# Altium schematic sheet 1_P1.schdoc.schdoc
size 309 x 223 mm; Symbol: Sheet-Symbol_A4; Device: Sheet-Symbol_A4; @Page Name: P1; @Create Date: 2023-12-06; @Page Count: 1; @Page No: 1; @Project Name: TauKeyboard; @Schematic Name: KeyboardCore; @Update Date: 2023-12-06; Company: 嘉立创EDA; Page Size: A4; Version: V1.0
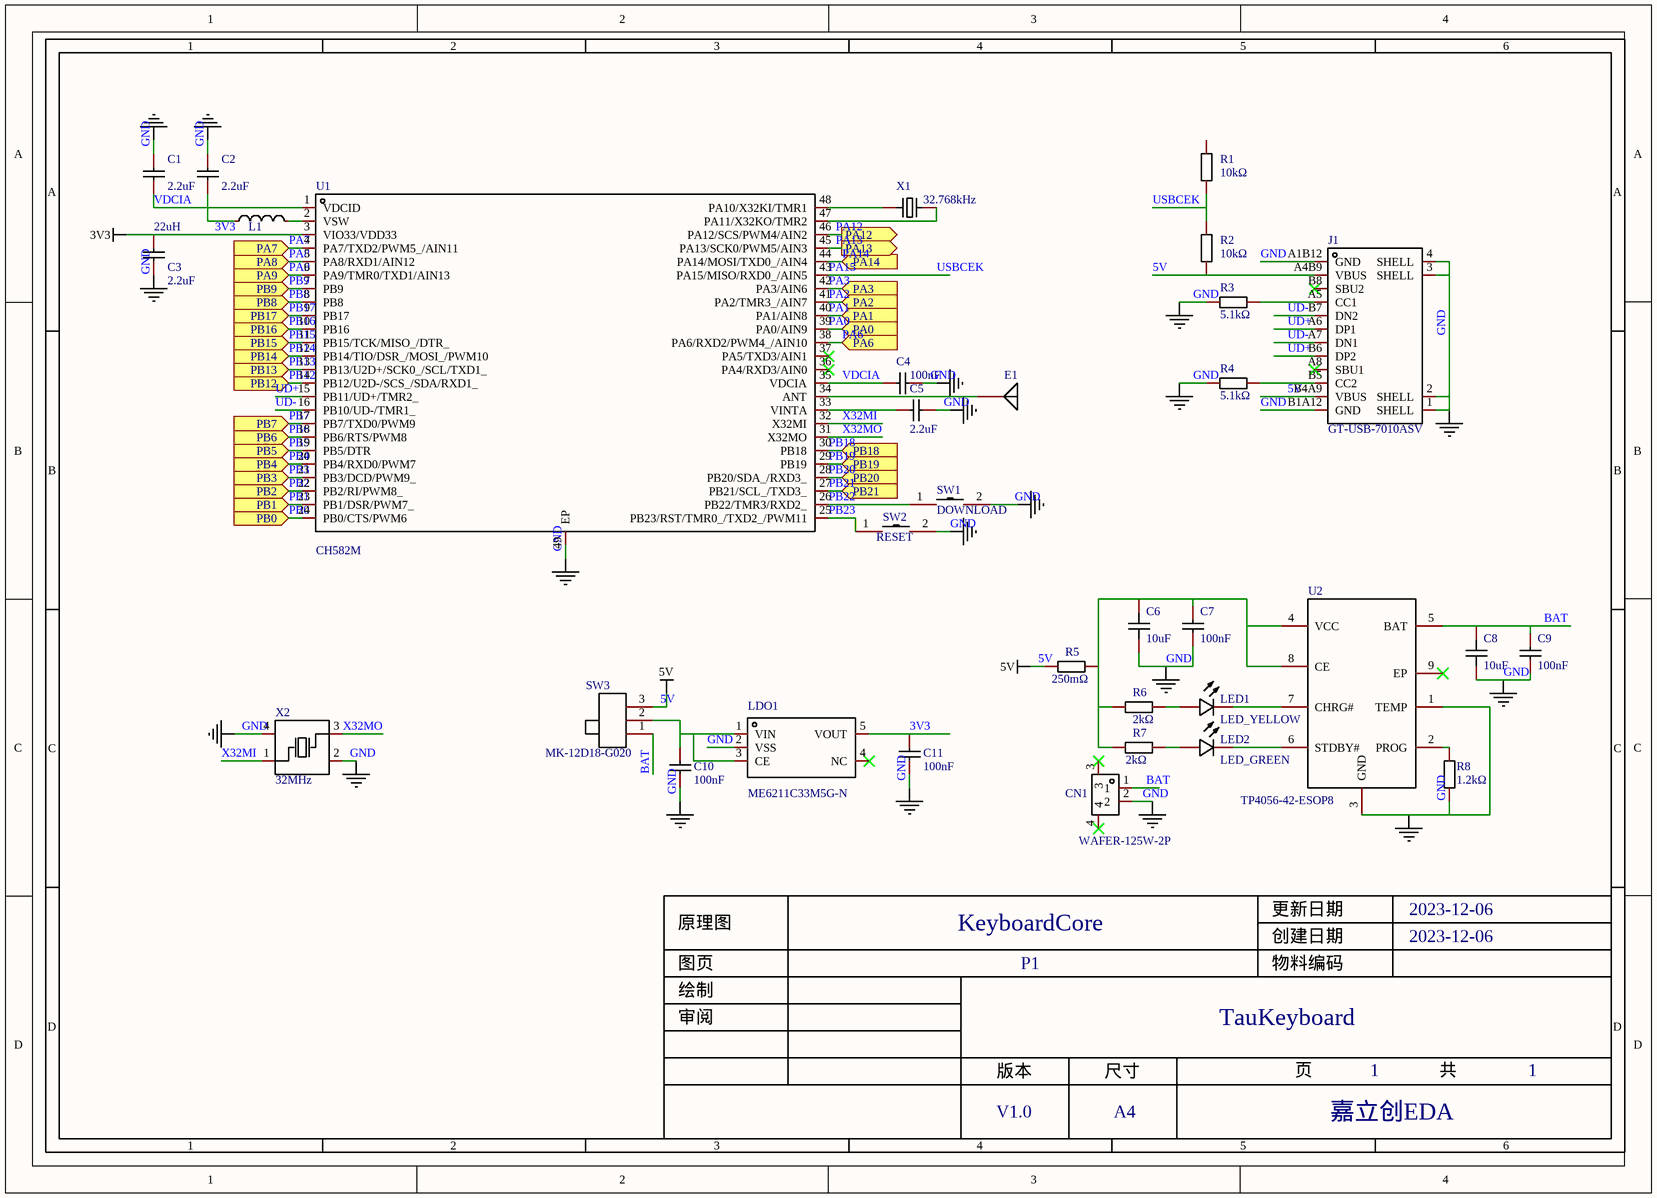
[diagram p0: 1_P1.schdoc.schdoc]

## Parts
C1  2.2uF  [C0603]
C2  2.2uF  [C0603]
C3  2.2uF  [C0603]
C4  100nF  [C0603]
C5  2.2uF  [C0603]
C6  10uF  [C0805]
C7  100nF  [C0603]
C8  10uF  [C0805]
C9  100nF  [C0603]
C10  100nF  [C0603]
C11  100nF  [C0603]
CN1  WAFER-125W-2P  [CONN-SMD_WAFER-125W-2P]
E1  Antenna  [Onboard Antenna]  (value not drawn)
J1  GT-USB-7010ASV  [USB-C-SMD_G-SWITCH_GT-USB-7010ASV]
L1  22uH  [IND-SMD_L3.0-W3.0_FNR30XXS]
LDO1  ME6211C33M5G-N  [SOT-23-5_L3.0-W1.7-P0.95-LS2.8-BL]
LED1  LED_YELLOW  [LED0603-RD]
LED2  LED_GREEN  [LED0603-RD]
R1  10kΩ  [R0603]
R2  10kΩ  [R0603]
R3  5.1kΩ  [R0603]
R4  5.1kΩ  [R0603]
R5  250mΩ  [R2010]
R6  2kΩ  [R0603]
R7  2kΩ  [R0603]
R8  1.2kΩ  [R0603]
SW1  DOWNLOAD  [SW-SMD_L6.0-W3.3-LS8.0]
SW2  RESET  [SW-SMD_L6.0-W3.3-LS8.0]
SW3  MK-12D18-G020  [SW-TH_MK-12D18-G040]
U1  CH582M  [QFN-48_L5.0-W5.0-P0.35-BL-EP]
U2  TP4056-42-ESOP8  [ESOP-8_L4.9-W3.9-P1.27-LS6.0-BL-EP]
X1  32.768kHz  [OSC-SMD_L3.2-W1.5]
X2  32MHz  [CRYSTAL-SMD_4P-L3.2-W2.5-BL]

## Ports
PA0 (in), PA1 (in), PA2 (in), PA3 (in), PA6 (in), PA7 (in), PA8 (in), PA9 (in), PA12 (out), PA13 (out), PA14 (in), PB0 (in), PB1 (in), PB2 (in), PB3 (in), PB4 (in), PB5 (in), PB6 (in), PB7 (in), PB8 (in), PB9 (in), PB12 (in), PB13 (in), PB14 (in), PB15 (in), PB16 (in), PB17 (in), PB18 (in), PB19 (in), PB20 (in), PB21 (in)

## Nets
3V3: C3.2 C11.2 LDO1.5(VOUT) U1.3(VIO33/VDD33)
5V: J1.A4B9(VBUS) J1.B4A9(VBUS) R2.1 R5.1 SW3.3
GND: C1.2 C2.2 C3.1 C4.2 C5.2 C6.1 C7.1 C8.1 C9.1 C10.1 C11.1 CN1.2 J1.1(SHELL) J1.2(SHELL) J1.3(SHELL) J1.4(SHELL) J1.A1B12(GND) J1.B1A12(GND) LDO1.2(VSS) R3.1 R4.1 R8.1 SW1.2 SW2.2 U1.49(EP) U2.1(TEMP) U2.3(GND) X2.2(GND) X2.4(GND)
BAT: C8.2 C9.2 CN1.1 SW3.1 U2.5(BAT)
PA0: U1.39(PA0/AIN9) ; port PA0
PA1: U1.40(PA1/AIN8) ; port PA1
PA2: U1.41(PA2/TMR3_/AIN7) ; port PA2
PA3: U1.42(PA3/AIN6) ; port PA3
PA6: U1.38(PA6/RXD2/PWM4_/AIN10) ; port PA6
PA7: U1.4(PA7/TXD2/PWM5_/AIN11) ; port PA7
PA8: U1.5(PA8/RXD1/AIN12) ; port PA8
PA9: U1.6(PA9/TMR0/TXD1/AIN13) ; port PA9
PA12: U1.46(PA12/SCS/PWM4/AIN2) ; port PA12
PA13: U1.45(PA13/SCK0/PWM5/AIN3) ; port PA13
PA14: U1.44(PA14/MOSI/TXD0_/AIN4) ; port PA14
PA15: R1.1 R2.2 U1.43(PA15/MISO/RXD0_/AIN5)  [also labelled USBCEK]
PB0: U1.24(PB0/CTS/PWM6) ; port PB0
PB1: U1.23(PB1/DSR/PWM7_) ; port PB1
PB2: U1.22(PB2/RI/PWM8_) ; port PB2
PB3: U1.21(PB3/DCD/PWM9_) ; port PB3
PB4: U1.20(PB4/RXD0/PWM7) ; port PB4
PB5: U1.19(PB5/DTR) ; port PB5
PB6: U1.18(PB6/RTS/PWM8) ; port PB6
PB7: U1.17(PB7/TXD0/PWM9) ; port PB7
PB8: U1.8(PB8) ; port PB8
PB9: U1.7(PB9) ; port PB9
PB12: U1.14(PB12/U2D-/SCS_/SDA/RXD1_) ; port PB12
PB13: U1.13(PB13/U2D+/SCK0_/SCL/TXD1_) ; port PB13
PB14: U1.12(PB14/TIO/DSR_/MOSI_/PWM10) ; port PB14
PB15: U1.11(PB15/TCK/MISO_/DTR_) ; port PB15
PB16: U1.10(PB16) ; port PB16
PB17: U1.9(PB17) ; port PB17
PB18: U1.30(PB18) ; port PB18
PB19: U1.29(PB19) ; port PB19
PB20: U1.28(PB20/SDA_/RXD3_) ; port PB20
PB21: U1.27(PB21/SCL_/TXD3_) ; port PB21
PB22: SW1.1 U1.26(PB22/TMR3/RXD2_)
PB23: SW2.1 U1.25(PB23/RST/TMR0_/TXD2_/PWM11)
UD+: J1.A6(DP1) J1.B6(DP2) U1.15(PB11/UD+/TMR2_)
UD-: J1.A7(DN1) J1.B7(DN2) U1.16(PB10/UD-/TMR1_)
VDCIA: C1.1 C2.1 C4.1 L1.1 U1.1(VDCID) U1.35(VDCIA)
X32MI: U1.32(X32MI) X2.1(OSC1)
X32MO: U1.31(X32MO) X2.3(OSC2)
NetC5_1: C5.1 U1.33(VINTA)
NetC6_2: C6.2 C7.2 R5.2 R6.1 R7.1 U2.4(VCC) U2.8(CE)
NetC10_2: C10.2 LDO1.1(VIN) LDO1.3(CE) SW3.2
NetE1_1: E1.1(A) U1.34(ANT)
NetJ1_A5: J1.A5(CC1) R3.2
NetJ1_B5: J1.B5(CC2) R4.2
NetL1_2: L1.2 U1.2(VSW)
NetLED1_1: LED1.1(K) U2.7(CHRG#)
NetLED1_2: LED1.2(A) R6.2
NetLED2_1: LED2.1(K) U2.6(STDBY#)
NetLED2_2: LED2.2(A) R7.2
NetR8_2: R8.2 U2.2(PROG)
NetU1_47: U1.47(PA11/X32KO/TMR2) X1.1
NetU1_48: U1.48(PA10/X32KI/TMR1) X1.2

Not connected (* = marked no-connect by the designer): CN1 3* 4*; J1 A8(SBU1)* B8(SBU2)*; LDO1 4(NC)*; R1 2; U1 36(PA4/RXD3/AIN0)* 37(PA5/TXD3/AIN1)*; U2 9(EP)*

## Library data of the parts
C1-C3 C5 = 0603B225K250NT: 容值:2.2uF;精度:±10%;额定电压:25V;材质(温度系数):X7R;; Manufacturer: FH(风华); Add into BOM: yes; Tolerance: ±10%; Voltage Rated: 25V; Temperature Coefficient: X7R
C4 C7 C9-C11 = 0603B104K500NT: 容值:100nF;精度:±10%;额定电压:50V;材质(温度系数):X7R;; Manufacturer: FH(风华); Add into BOM: yes; Tolerance: ±10%; Voltage Rated: 50V; Temperature Coefficient: X7R
C6 C8 = 0805B106K100NT: 容值:10uF;精度:±10%;额定电压:10V;材质(温度系数):X7R;; Manufacturer: FH(风华); Add into BOM: yes; Tolerance: ±10%; Voltage Rated: 10V; Temperature Coefficient: X7R
CN1 = WAFER-125W-2P: 插针结构:1x2P;间距:1.25mm;公母:公;安装方式:卧贴;行距:-;排数:1;每排PIN数:2;参考系列:-;额定电流:1A;工作温度范围:-25℃~+85℃;; Manufacturer: XUNPU(讯普); Add into BOM: yes; Pins Structure: 1x2P; Pitch: 1.25mm; Gender: 公; Number of PINs Per Row: 2; Current Rating (Max): 1A
E1 = Antenna: Add into BOM: yes
J1 = GT-USB-7010ASV: 连接器类型:Type-C;标准:USB 2.0;公母:母;触点数量:16P;端口数量:1;安装方式:卧贴;额定电流 - 电源:3A;触头材质:高导铜;触头镀层:金;工作温度范围:-40℃~+85℃;焊接温度(最大值):-;; Manufacturer: G-Switch(品赞); Add into BOM: yes; Connector Type: Type-C; Gender: 母; Number of Contacts: 16P; Number of Ports: 1; Current Rating - Power (Max): 3A
L1 = FNR3015S220MT: 电感值:22uH;精度:±20%;额定电流:690mA;饱和电流(Isat):680mA;; Manufacturer: cjiang(长江微电); Add into BOM: yes; Tolerance: ±20%; Rated Current: 690mA; DC Resistance (DCR): 598mΩ; Saturation Current (Isat): 680mA
LDO1 = ME6211C33M5G-N: 输出类型:固定;输出极性:正;最大输入电压:6V;输出电压:3.3V;输出电流:500mA;电源纹波抑制比(PSRR):70dB;; Manufacturer: MICRONE(南京微盟); Add into BOM: yes; Output Type: 固定; Output Polarity: 正; Number of Outputs: 1; Maximum Input Voltage: 6V; Output Voltage: 3.3V; Dropout Voltage: 260mV@(200mA); Output Current: 500mA; Power Supply Rejection Ratio (PSRR): 70dB
LED1 = NCD0603Y1: 发光颜色:黄色;功率:65mW;透镜颜色:无色透明;主波长:586nm~595nm;发光强度:80mcd~220mcd;发光角度:130°;工作温度:-30℃~+85℃;; Manufacturer: 国星光电; Symbol: FC-D1608HYK-588J; Add into BOM: yes; Emitted Color: 黄色; Forward Voltage (VF): 1.6V~2.6V; Forward Current: 20mA; Power Dissipation: 65mW; Lens Color: 无色透明; Viewing Angle: 130°
LED2 = NCD0603G1: 发光颜色:翠绿色;功率:72mW;透镜颜色:无色透明;主波长:515nm~530nm;发光强度:330mcd~900mcd;发光角度:130°;工作温度:-30℃~+85℃;; Manufacturer: 国星光电; Symbol: FC-D1608UGK-520D10; Add into BOM: yes; Emitted Color: 翠绿色; Forward Voltage (VF): 2.6V~3.6V; Forward Current: 10mA; Power Dissipation: 72mW; Lens Color: 无色透明; Viewing Angle: 130°
R1 R2 = RS-03K1002FT: 精度:±1%;温度系数:±100ppm/℃;阻值:10kΩ;功率:100mW;最大工作电压:50V;工作温度范围:-55℃~+155℃;; Manufacturer: FH(风华); Add into BOM: yes; Tolerance: ±1%; Power(Watts): 100mW; Overload Voltage (Max): 50V
R3 R4 = RS-03K5101FT: 阻值:5.1kΩ;精度:±1%;功率:100mW;温度系数:±100ppm/℃;; Manufacturer: FH(风华); Add into BOM: yes; Tolerance: ±1%; Power(Watts): 100mW; Overload Voltage (Max): 50V
R5 = RL2010JK-070R25L: Manufacturer: YAGEO(国巨); Add into BOM: yes
R6 R7 = RS-03K2001FT: 阻值:2kΩ;精度:±1%;功率:100mW;温度系数:±100ppm/℃;最大工作电压:50V;工作温度范围:-55℃~+155℃;; Manufacturer: FH(风华); Add into BOM: yes; Tolerance: ±1%; Power(Watts): 100mW; Overload Voltage (Max): 50V
R8 = RC0603FR-071K2L: 电阻类型:厚膜电阻;阻值:1.2kΩ;精度:±1%;功率:100mW;; Manufacturer: YAGEO(国巨); Add into BOM: yes; Tolerance: ±1%; Power(Watts): 100mW; Temperature Coefficient: ±100ppm/℃; Overload Voltage (Max): 75V
SW1 SW2 = TS-1101-C-W: 电路结构:单刀单掷;带支架:否;触点电流:50mA;额定电压(AC):-;额定电压(DC):12V;额定功率:-;安装方式:立贴;绝缘电阻:-;带灯:无;作用力:260gf;机械寿命:5万次;; Manufacturer: XKB Connectivity(中国星坤); Add into BOM: yes; Circuit: 单刀单掷; Actuator Style: 矩形按钮; Switch Length: 6mm; Switch Width: 3.6mm; Switch Height: 2.5mm; Strike Gundam: 否; Contact Current: 50mA; Voltage Rating (DC): 12V; Actuator/Cap Color: 白色带淡绿; With Lamp: 无; Operating Force: 260gf; Mechanical Life: 5万次
SW3 = MK-12D18-G020: Manufacturer: G-Switch(品赞); Add into BOM: yes
U1 = CH582M: CPU内核:RISC-V;CPU最大主频:80MHz;工作电压范围:2.3V~3.6V;程序存储容量:512KB;程序存储器类型:FLASH;RAM总容量:32KB;GPIO端口数量:40;; Manufacturer: WCH(南京沁恒); Add into BOM: yes; CPU Core: RISC-V; CPU Maximum Speed: 80MHz; Program Storage Size: 512KB; Program Memory Type: FLASH; RAM Size: 32KB; GPIO Ports Number: 40; ADC (Bit): 12bit; PWM (Bit): 26bit; 32Bit Timer: 4; I2C: 1; SPI: 2
U2 = TP4056-42-ESOP8: 锂电池充电芯片; Manufacturer: TOPPOWER(南京拓微); Symbol: TP4056; Add into BOM: yes
X1 = X321532768KGD2SI: 频率:32.768kHz;负载电容:12.5pF;频率公差:±20ppm;; Manufacturer: YXC(扬兴晶振); Add into BOM: yes; Crystal Type: 贴片无源晶振; Load Capacitance: 12.5pF; Frequency Tolerance: ±20ppm
X2 = X322532MOB4SI: 频率:32MHz;负载电容:12pF;频率公差:±10ppm;; Manufacturer: YXC(扬兴晶振); Add into BOM: yes; Crystal Type: 贴片无源晶振; Load Capacitance: 12pF; Frequency Tolerance: ±10ppm; Frequency Stability: ±30ppm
